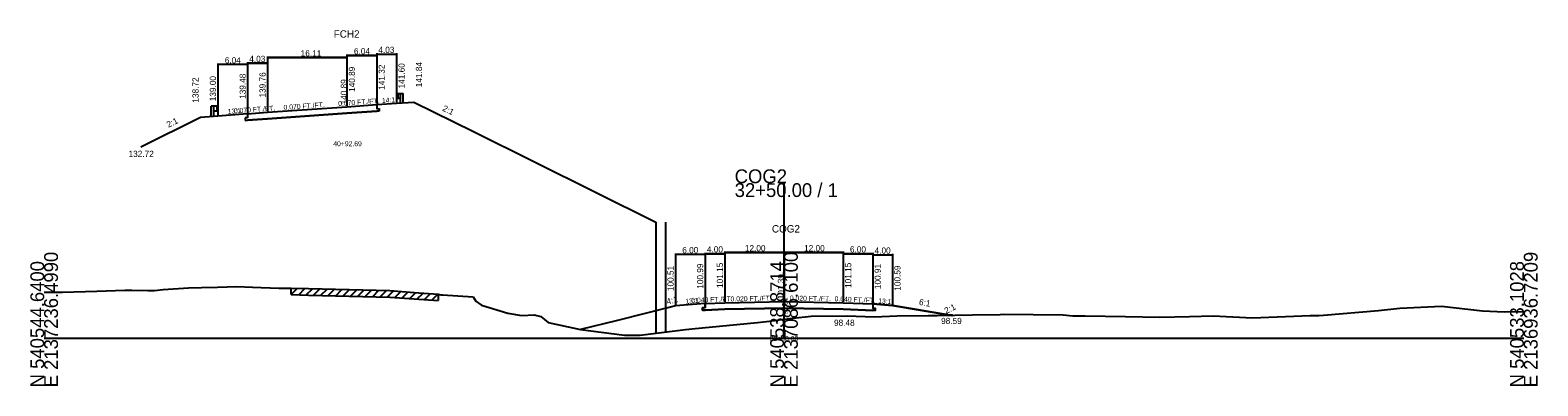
# Model space of a CAD drawing. Extents: x -13397 to 2303, y -10 to 39059.
# Drawn here: x 997.2 to 1302.8, y 4990.3 to 5062.4 of the extents above; entities that cross this region are included whole.
import ezdxf

# ---------------------------------------------------------------- set-up
doc = ezdxf.new("R2010")
doc.units = 0
for name, color, linetype in [('Level 20', 7, 'Continuous'), ('Level 5', 7, 'Continuous'), ('Level 53', 7, 'Continuous'), ('Level 54', 7, 'Continuous'), ('Level 55', 7, 'Continuous'), ('Level 7', 7, 'Continuous'), ('RD_GPK_XS_Cell', 7, 'Continuous'), ('RD_XS_EwShp', 7, 'Continuous'), ('RD_XS_ExGround', 7, 'Continuous'), ('RD_XS_ExPaveRet', 7, 'Continuous'), ('RD_XS_MedBWall', 7, 'Continuous'), ('RD_XS_Pave', 7, 'Continuous'), ('RD_XS_TX_Baseline', 7, 'Continuous'), ('RD_XS_TX_Elev_EX', 7, 'Continuous'), ('RD_XS_TX_Elev_PR', 7, 'Continuous'), ('RD_XS_TX_Station', 7, 'Continuous')]:
    doc.layers.add(name, color=color, linetype=linetype)

msp = doc.modelspace()

# ---------------------------------------------------------------- linework, layer by layer
at = {"layer": 'Level 20'}
for p, q in [((1045.28, 5057.04), (1045.28, 5045.96)), ((1045.28, 5057.04), (1045.28, 5045.96)), ((1045.28, 5057.04), (1045.28, 5045.96)), ((1045.28, 5057.04), (1045.28, 5045.96)), ((1045.28, 5056.84), (1061.39, 5056.84)), ((1045.28, 5056.84), (1061.39, 5056.84)), ((1061.39, 5056.84), (1045.28, 5056.84)), ((1061.39, 5056.84), (1045.28, 5056.84)), ((1061.39, 5057.47), (1061.39, 5047.09)), ((1061.39, 5057.47), (1061.39, 5047.09)), ((1061.39, 5057.47), (1061.39, 5047.09)), ((1061.39, 5057.27), (1067.42, 5057.27)), ((1067.42, 5057.27), (1061.39, 5057.27)), ((1067.42, 5057.27), (1061.39, 5057.27)), ((1061.39, 5057.04), (1061.39, 5047.09)), ((1061.39, 5057.04), (1061.39, 5047.09)), ((1061.39, 5057.04), (1061.39, 5047.09)), ((1061.39, 5057.04), (1061.39, 5047.09)), ((1067.42, 5057.75), (1067.42, 5047.52)), ((1067.42, 5057.55), (1071.45, 5057.55)), ((1067.42, 5057.47), (1067.42, 5047.52)), ((1067.42, 5057.47), (1067.42, 5047.52)), ((1067.42, 5057.47), (1067.42, 5047.52)), ((1071.45, 5057.75), (1071.45, 5047.8)), ((1035.21, 5055.63), (1035.21, 5045.2)), ((1041.25, 5055.43), (1035.21, 5055.43)), ((1041.25, 5055.91), (1041.25, 5045.68)), ((1041.25, 5055.91), (1041.25, 5045.68)), ((1041.25, 5055.91), (1041.25, 5045.68)), ((1041.25, 5055.71), (1045.28, 5055.71)), ((1041.25, 5055.71), (1045.28, 5055.71)), ((1045.28, 5055.71), (1041.25, 5055.71)), ((1041.25, 5055.63), (1041.25, 5045.68)), ((1045.28, 5055.91), (1045.28, 5045.96)), ((1045.28, 5055.91), (1045.28, 5045.96)), ((1045.28, 5055.91), (1045.28, 5045.96)), ((1033.87, 5045), (1033.87, 5046.99)), ((1034.43, 5046.99), (1033.87, 5046.99)), ((1034.43, 5045), (1034.43, 5046.99)), ((1034.98, 5046.99), (1034.43, 5046.99)), ((1034.98, 5046.99), (1034.98, 5046.01)), ((1035.06, 5046.91), (1034.98, 5046.92)), ((1035.19, 5046.81), (1035.07, 5046.91)), ((1045.28, 5045.76), (1061.39, 5046.89)), ((1061.39, 5046.89), (1067.42, 5047.32)), ((1067.42, 5047.32), (1071.45, 5047.6)), ((1067.42, 5047.32), (1067.42, 5046.48)), ((1071.45, 5047.6), (1074.97, 5047.84)), ((1071.48, 5049.41), (1071.59, 5049.5)), ((1071.48, 5049.31), (1071.59, 5049.22)), ((1071.48, 5048.88), (1071.59, 5048.97)), ((1071.48, 5048.78), (1071.59, 5048.69)), ((1071.6, 5049.51), (1071.68, 5049.52)), ((1071.6, 5048.68), (1071.68, 5048.67)), ((1071.61, 5049.17), (1071.61, 5049.02)), ((1071.68, 5049.58), (1071.68, 5048.61)), ((1071.68, 5049.58), (1072.23, 5049.58)), ((1071.68, 5048.61), (1072.23, 5048.61)), ((1072.23, 5047.6), (1072.23, 5049.58)), ((1072.23, 5049.58), (1072.79, 5049.58)), ((1072.79, 5047.6), (1072.79, 5049.58)), ((1074.97, 5047.84), (1087.05, 5041.84)), ((1031.69, 5044.72), (1019.6, 5038.72)), ((1035.21, 5045), (1031.69, 5044.72)), ((1034.98, 5046.01), (1034.43, 5046.01)), ((1035.06, 5046.09), (1034.98, 5046.07)), ((1035.05, 5046.58), (1035.05, 5046.42)), ((1035.19, 5046.71), (1035.07, 5046.62)), ((1035.19, 5046.28), (1035.07, 5046.38)), ((1035.19, 5046.18), (1035.07, 5046.09)), ((1041.25, 5045.48), (1035.21, 5045)), ((1041.25, 5044.64), (1040.75, 5044.61)), ((1040.75, 5044.61), (1040.75, 5044.11)), ((1040.75, 5044.11), (1041.25, 5044.14)), ((1041.25, 5045.48), (1045.28, 5045.76)), ((1041.25, 5045.48), (1041.25, 5044.64)), ((1045.28, 5044.43), (1041.25, 5044.14)), ((1045.28, 5044.43), (1041.25, 5044.14)), ((1041.25, 5044.14), (1045.28, 5044.43)), ((1061.39, 5045.56), (1045.28, 5044.43)), ((1061.39, 5045.56), (1045.28, 5044.43)), ((1045.28, 5044.43), (1061.39, 5045.56)), ((1045.28, 5044.43), (1061.39, 5045.56)), ((1067.42, 5045.98), (1061.39, 5045.56)), ((1061.39, 5045.56), (1067.42, 5045.98)), ((1061.39, 5045.56), (1067.42, 5045.98)), ((1067.42, 5046.48), (1067.93, 5046.52)), ((1067.93, 5046.02), (1067.42, 5045.98)), ((1067.93, 5046.52), (1067.93, 5046.02)), ((1087.05, 5041.84), (1124, 5023.49))]:
    msp.add_line(p, q, dxfattribs=at)
for centre, radius, start, end in [((1035.06, 5046.89), 0.026, 50.9495, 90), ((1035.14, 5046.76), 0.0651, 309.0337, 50.9664), ((1071.52, 5049.36), 0.0651, 129.0336, 230.9663), ((1071.52, 5048.83), 0.0651, 129.0336, 230.9663), ((1071.54, 5049.02), 0.0651, 302.9895, 0), ((1071.6, 5049.48), 0.026, 90, 129.0505), ((1071.54, 5049.17), 0.0651, 0, 45), ((1071.6, 5048.71), 0.026, 230.9496, 270), ((1035.12, 5046.58), 0.0651, 135, 180), ((1035.12, 5046.42), 0.0651, 180, 237.0105), ((1035.06, 5046.11), 0.026, 270, 309.0504), ((1035.14, 5046.23), 0.0651, 309.0337, 50.9664)]:
    msp.add_arc(centre, radius, start, end, dxfattribs=at)
at = {"layer": 'Level 5'}
for p, q in [((1134, 5006.16), (1133.5, 5006.14)), ((1133.5, 5006.14), (1133.5, 5005.64)), ((1133.5, 5005.64), (1134, 5005.66)), ((1134, 5006.99), (1134, 5006.16)), ((1138, 5005.82), (1134, 5005.66)), ((1138, 5005.82), (1134, 5005.66)), ((1138, 5005.82), (1134, 5005.66)), ((1134, 5005.66), (1138, 5005.82)), ((1150, 5006.06), (1138, 5005.82)), ((1150, 5006.06), (1138, 5005.82)), ((1150, 5006.06), (1138, 5005.82)), ((1138, 5005.82), (1150, 5006.06)), ((1138, 5005.82), (1150, 5006.06)), ((1162, 5005.82), (1150, 5006.06)), ((1162, 5005.82), (1150, 5006.06)), ((1150, 5006.06), (1162, 5005.82)), ((1150, 5006.06), (1162, 5005.82)), ((1150, 5006.06), (1162, 5005.82)), ((1168, 5005.58), (1162, 5005.82)), ((1162, 5005.82), (1168, 5005.58)), ((1162, 5005.82), (1168, 5005.58)), ((1162, 5005.82), (1168, 5005.58)), ((1168, 5006.91), (1168, 5006.08)), ((1168, 5006.08), (1168.5, 5006.06)), ((1168.5, 5005.56), (1168, 5005.58)), ((1168.5, 5006.06), (1168.5, 5005.56))]:
    msp.add_line(p, q, dxfattribs=at)
at = {"layer": 'Level 54'}
for p, q in [((1128, 5017.14), (1128, 5006.71)), ((1134, 5016.94), (1128, 5016.94)), ((1134, 5017.3), (1134, 5007.19)), ((1134, 5017.3), (1134, 5007.19)), ((1134, 5017.3), (1134, 5007.19)), ((1134, 5017.3), (1134, 5007.19)), ((1134, 5017.14), (1134, 5007.19)), ((1134, 5017.1), (1138, 5017.1)), ((1134, 5017.1), (1138, 5017.1)), ((1134, 5017.1), (1138, 5017.1)), ((1138, 5017.1), (1134, 5017.1)), ((1138, 5017.54), (1138, 5007.35)), ((1138, 5017.54), (1138, 5007.35)), ((1138, 5017.54), (1138, 5007.35)), ((1138, 5017.54), (1138, 5007.35)), ((1138, 5017.54), (1138, 5007.35)), ((1138, 5017.34), (1150, 5017.34)), ((1138, 5017.34), (1150, 5017.34)), ((1138, 5017.34), (1150, 5017.34)), ((1150, 5017.34), (1138, 5017.34)), ((1150, 5017.34), (1138, 5017.34)), ((1138, 5017.3), (1138, 5007.35)), ((1138, 5017.3), (1138, 5007.35)), ((1138, 5017.3), (1138, 5007.35)), ((1138, 5017.3), (1138, 5007.35)), ((1150, 5017.54), (1150, 5007.59)), ((1150, 5017.54), (1150, 5007.59)), ((1150, 5017.54), (1150, 5007.59)), ((1150, 5017.54), (1150, 5007.59)), ((1150, 5017.54), (1150, 5007.59)), ((1150, 5017.54), (1150, 5007.59)), ((1150, 5017.54), (1150, 5007.59)), ((1150, 5017.54), (1150, 5007.59)), ((1150, 5017.54), (1150, 5007.59)), ((1150, 5017.54), (1150, 5007.59)), ((1150, 5017.34), (1162, 5017.34)), ((1150, 5017.34), (1162, 5017.34)), ((1162, 5017.34), (1150, 5017.34)), ((1162, 5017.34), (1150, 5017.34)), ((1162, 5017.34), (1150, 5017.34)), ((1162, 5017.54), (1162, 5007.35)), ((1162, 5017.54), (1162, 5007.35)), ((1162, 5017.54), (1162, 5007.35)), ((1162, 5017.54), (1162, 5007.35)), ((1162, 5017.54), (1162, 5007.35)), ((1162, 5017.3), (1162, 5007.35)), ((1162, 5017.3), (1162, 5007.35)), ((1162, 5017.3), (1162, 5007.35)), ((1162, 5017.3), (1162, 5007.35)), ((1162, 5017.1), (1168, 5017.1)), ((1168, 5017.1), (1162, 5017.1)), ((1168, 5017.1), (1162, 5017.1)), ((1168, 5017.1), (1162, 5017.1)), ((1168, 5017.3), (1168, 5007.11)), ((1168, 5017.3), (1168, 5007.11)), ((1168, 5017.3), (1168, 5007.11)), ((1168, 5017.3), (1168, 5007.11)), ((1168, 5017.06), (1168, 5007.11)), ((1168, 5016.86), (1172, 5016.86)), ((1172, 5017.06), (1172, 5006.79))]:
    msp.add_line(p, q, dxfattribs=at)
at = {"layer": 'Level 7'}
for p, q in [((1128, 5006.51), (1126, 5006.01)), ((1126, 5006.01), (1126, 5001.24)), ((1134, 5006.99), (1128, 5006.51)), ((1168, 5006.91), (1172, 5006.59)), ((1172, 5006.59), (1184, 5004.59)), ((1184, 5004.59), (1184.13, 5004.65))]:
    msp.add_line(p, q, dxfattribs=at)
at = {"layer": 'RD_GPK_XS_Cell'}
for p, q in [((1150, 5000), (1150, 5031.39)), ((1000, 5000), (1150, 5000)), ((1150, 5000), (1300, 5000))]:
    msp.add_line(p, q, dxfattribs=at)
at = {"layer": 'RD_XS_EwShp'}
for points in [[(1117.63, 5000.6), (1119.5, 5000.57), (1120.82, 5000.6), (1130.02, 5001.73), (1130.76, 5001.83), (1131.32, 5001.88), (1144.64, 5003.16), (1147.04, 5003.42), (1150, 5003.81), (1151.78, 5004.05), (1155.48, 5004.43), (1162.82, 5004.48), (1168.26, 5004.33), (1172.92, 5004.51), (1179.27, 5004.6), (1181.05, 5004.6), (1183.67, 5004.65), (1172, 5006.59), (1168, 5006.91), (1168, 5006.08), (1168.5, 5006.06), (1168.5, 5005.56), (1168, 5005.58), (1162, 5005.82), (1150, 5006.06), (1138, 5005.82), (1134, 5005.66), (1133.5, 5005.64), (1133.5, 5006.14), (1134, 5006.16), (1134, 5006.99), (1128, 5006.51), (1116, 5003.51), (1108.76, 5001.7)], [(1183.67, 5004.65), (1184, 5004.59), (1184.13, 5004.65)]]:
    msp.add_lwpolyline(points, close=True, dxfattribs=at)
at = {"layer": 'RD_XS_ExGround'}
for p, q in [((1024.13, 5009.83), (1029.29, 5010.15)), ((1029.29, 5010.15), (1031.93, 5010.26)), ((1031.93, 5010.26), (1035.15, 5010.34)), ((1035.15, 5010.34), (1039.05, 5010.46)), ((1039.05, 5010.46), (1042.23, 5010.31)), ((1042.23, 5010.31), (1047.59, 5010.14)), ((1047.59, 5010.14), (1050.11, 5010.12)), ((1000, 5009.28), (1002.01, 5009.29)), ((1002.01, 5009.29), (1003.71, 5009.31)), ((1003.71, 5009.31), (1010.71, 5009.49)), ((1010.71, 5009.49), (1016.35, 5009.67)), ((1016.35, 5009.67), (1017.74, 5009.71)), ((1017.74, 5009.71), (1020.99, 5009.65)), ((1020.99, 5009.65), (1022.4, 5009.62)), ((1022.4, 5009.62), (1024.13, 5009.83)), ((1050.11, 5010.12), (1053.62, 5010.02)), ((1053.62, 5010.02), (1070.07, 5009.61)), ((1070.07, 5009.61), (1075.03, 5009.26)), ((1075.03, 5009.26), (1079.88, 5008.89)), ((1079.88, 5008.89), (1080.4, 5008.79)), ((1080.4, 5008.79), (1080.74, 5008.76)), ((1080.74, 5008.76), (1086.97, 5008.38)), ((1086.97, 5008.38), (1087.49, 5007.46)), ((1087.49, 5007.46), (1088.67, 5006.64)), ((1088.67, 5006.64), (1094.01, 5005.07)), ((1094.01, 5005.07), (1096.79, 5004.57)), ((1096.79, 5004.57), (1099.44, 5004.71)), ((1099.44, 5004.71), (1099.91, 5004.6)), ((1099.91, 5004.6), (1100.7, 5004.38)), ((1100.7, 5004.38), (1102.16, 5003.17)), ((1150, 5003.81), (1151.78, 5004.05)), ((1151.78, 5004.05), (1155.48, 5004.43)), ((1155.48, 5004.43), (1162.82, 5004.48)), ((1162.82, 5004.48), (1168.26, 5004.33)), ((1168.26, 5004.33), (1172.92, 5004.51)), ((1172.92, 5004.51), (1179.27, 5004.6)), ((1179.27, 5004.6), (1181.05, 5004.6)), ((1181.05, 5004.6), (1188.19, 5004.72)), ((1188.19, 5004.72), (1193.83, 5004.8)), ((1193.83, 5004.8), (1194.41, 5004.82)), ((1194.41, 5004.82), (1206.61, 5004.68)), ((1206.61, 5004.68), (1208.59, 5004.51)), ((1208.59, 5004.51), (1211.05, 5004.52)), ((1211.05, 5004.52), (1219.27, 5004.37)), ((1219.27, 5004.37), (1226.19, 5004.26)), ((1226.19, 5004.26), (1232.18, 5004.35)), ((1232.18, 5004.35), (1237.01, 5004.49)), ((1237.01, 5004.49), (1244.96, 5004.09)), ((1244.96, 5004.09), (1256.66, 5004.58)), ((1256.66, 5004.58), (1257.74, 5004.58)), ((1257.74, 5004.58), (1258.46, 5004.59)), ((1258.46, 5004.59), (1259.39, 5004.64)), ((1259.39, 5004.64), (1270.53, 5005.6)), ((1270.53, 5005.6), (1274.83, 5006.07)), ((1274.83, 5006.07), (1283.31, 5006.45)), ((1283.31, 5006.45), (1291.63, 5005.54)), ((1291.63, 5005.54), (1296.09, 5005.29)), ((1296.09, 5005.29), (1300, 5005.35)), ((1102.16, 5003.17), (1108.71, 5001.71)), ((1108.71, 5001.71), (1117.63, 5000.6)), ((1120.82, 5000.6), (1130.02, 5001.73)), ((1130.02, 5001.73), (1130.76, 5001.83)), ((1130.76, 5001.83), (1131.32, 5001.88)), ((1131.32, 5001.88), (1144.64, 5003.16)), ((1144.64, 5003.16), (1147.04, 5003.42)), ((1147.04, 5003.42), (1150, 5003.81)), ((1117.63, 5000.6), (1119.5, 5000.57)), ((1119.5, 5000.57), (1120.82, 5000.6))]:
    msp.add_line(p, q, dxfattribs=at)
at = {"layer": 'RD_XS_ExPaveRet'}
for p, q in [((1050.11, 5008.82), (1050.11, 5010.12)), ((1050.11, 5008.82), (1051.38, 5010.08)), ((1050.11, 5008.82), (1053.62, 5008.72)), ((1051.61, 5008.78), (1052.88, 5010.04)), ((1053.11, 5008.73), (1054.38, 5010)), ((1053.62, 5008.72), (1070.07, 5008.31)), ((1054.61, 5008.69), (1055.88, 5009.96)), ((1056.11, 5008.66), (1057.38, 5009.93)), ((1057.61, 5008.62), (1058.88, 5009.89)), ((1059.11, 5008.58), (1060.38, 5009.85)), ((1060.61, 5008.55), (1061.88, 5009.81)), ((1062.11, 5008.51), (1063.38, 5009.78)), ((1063.61, 5008.47), (1064.88, 5009.74)), ((1065.11, 5008.43), (1066.38, 5009.7)), ((1066.61, 5008.4), (1067.88, 5009.67)), ((1068.11, 5008.36), (1069.38, 5009.63)), ((1069.61, 5008.32), (1070.85, 5009.56)), ((1070.07, 5008.31), (1075.03, 5007.96)), ((1071.11, 5008.24), (1072.33, 5009.45)), ((1072.61, 5008.13), (1073.83, 5009.34)), ((1074.11, 5008.02), (1075.33, 5009.24)), ((1075.03, 5007.96), (1079.88, 5007.59)), ((1075.61, 5007.92), (1076.82, 5009.12)), ((1077.11, 5007.8), (1078.32, 5009.01)), ((1078.61, 5007.69), (1079.82, 5008.9)), ((1079.88, 5008.89), (1079.88, 5007.59))]:
    msp.add_line(p, q, dxfattribs=at)
at = {"layer": 'RD_XS_MedBWall'}
for p, q in [((1124, 5023.49), (1124, 5000.99)), ((1126, 5023.49), (1126, 5006.01))]:
    msp.add_line(p, q, dxfattribs=at)
at = {"layer": 'RD_XS_Pave'}
for p, q in [((1134, 5006.99), (1138, 5007.15)), ((1138, 5007.15), (1150, 5007.39)), ((1150, 5007.39), (1162, 5007.15)), ((1162, 5007.15), (1168, 5006.91))]:
    msp.add_line(p, q, dxfattribs=at)

# ---------------------------------------------------------------- texts
at = {"layer": 'Level 20'}
for s, height, p in [('FCH2', 1.5, (1058.7, 5060.89)), ('4.03', 1.25, (1067.76, 5057.8)), ('6.04', 1.25, (1036.62, 5055.68)), ('4.03', 1.25, (1041.59, 5055.96)), ('4.03', 1.25, (1041.59, 5055.96)), ('4.03', 1.25, (1041.59, 5055.96)), ('16.11', 1.25, (1052.01, 5057.09)), ('16.11', 1.25, (1052.01, 5057.09)), ('16.11', 1.25, (1052.01, 5057.09)), ('16.11', 1.25, (1052.01, 5057.09)), ('6.04', 1.25, (1062.8, 5057.52)), ('6.04', 1.25, (1062.8, 5057.52)), ('6.04', 1.25, (1062.8, 5057.52)), ('132.72', 1.25, (1017.11, 5036.72)), ('40+92.69', 1, (1058.61, 5038.89))]:
    msp.add_text(s, height=height, dxfattribs=at).set_placement(p)
for s, height, rotation, p in [('139.00', 1.25, 90, (1034.83, 5048)), ('139.48', 1.25, 90, (1040.87, 5048.48)), ('139.76', 1.25, 90, (1044.9, 5048.76)), ('139.76', 1.25, 90, (1044.9, 5048.76)), ('140.89', 1.25, 90, (1063.02, 5049.89)), ('140.89', 1.25, 90, (1063.02, 5049.89)), ('141.32', 1.25, 90, (1069.06, 5050.32)), ('141.60', 1.25, 90, (1073.08, 5050.6)), ('141.84', 1.25, 90, (1076.61, 5050.84)), ('138.72', 1.25, 90, (1031.3, 5047.72)), (' 140.89', 1.25, 90, (1061.39, 5046.89)), ('0.070 FT./FT.', 1, 4.0129, (1038.51, 5045.54)), ('0.070 FT./FT.', 1, 4.0129, (1038.51, 5045.54)), ('0.070 FT./FT.', 1, 4.0129, (1038.51, 5045.54)), ('0.070 FT./FT.', 1, 4.0147, (1048.57, 5046.24)), ('0.070 FT./FT.', 1, 4.0147, (1048.57, 5046.24)), ('0.070 FT./FT.', 1, 4.0147, (1048.57, 5046.24)), ('0.070 FT./FT.', 1, 4.0147, (1048.57, 5046.24)), ('0.070 FT./FT.', 1, 4.0167, (1059.65, 5047.02)), ('0.070 FT./FT.', 1, 4.0167, (1059.65, 5047.02)), ('0.070 FT./FT.', 1, 4.0167, (1059.65, 5047.02)), ('14:1', 1, 3.9907, (1068.52, 5047.64)), ('2:1', 1.25, 333.5843, (1080.62, 5046.16)), ('2:1', 1.25, 26.4087, (1025.2, 5042.61)), ('13:1', 1, 4.5429, (1037.26, 5045.41))]:
    msp.add_text(s, height=height, rotation=rotation, dxfattribs=at).set_placement(p)
at = {"layer": 'Level 53'}
for s, rotation, p in [('100.51', 90, (1127.62, 5009.51)), ('100.99', 90, (1133.62, 5009.99)), ('101.15', 90, (1137.63, 5010.15)), ('101.15', 90, (1137.63, 5010.15)), ('101.15', 90, (1137.63, 5010.15)), ('101.15', 90, (1163.62, 5010.15)), ('101.15', 90, (1163.62, 5010.15)), ('101.15', 90, (1163.62, 5010.15)), ('100.91', 90, (1169.62, 5009.91)), ('100.59', 90, (1173.62, 5009.59)), ('4:1', 14.0362, (1126.34, 5006.75)), ('6:1', 350.5377, (1177.3, 5006.72))]:
    msp.add_text(s, height=1.25, rotation=rotation, dxfattribs=at).set_placement(p)
for s, p in [('98.59', (1181.85, 5002.84)), ('98.48', (1160.14, 5002.48))]:
    msp.add_text(s, height=1.25, dxfattribs=at).set_placement(p)
at = {"layer": 'Level 54'}
for s, p in [('6.00', (1129.37, 5017.19)), ('4.00', (1134.37, 5017.35)), ('4.00', (1134.37, 5017.35)), ('4.00', (1134.37, 5017.35)), ('4.00', (1134.37, 5017.35)), ('12.00', (1142.07, 5017.59)), ('12.00', (1142.07, 5017.59)), ('12.00', (1142.07, 5017.59)), ('12.00', (1142.07, 5017.59)), ('12.00', (1142.07, 5017.59)), ('12.00', (1154.07, 5017.59)), ('12.00', (1154.07, 5017.59)), ('12.00', (1154.07, 5017.59)), ('12.00', (1154.07, 5017.59)), ('12.00', (1154.07, 5017.59)), ('6.00', (1163.37, 5017.35)), ('6.00', (1163.37, 5017.35)), ('6.00', (1163.37, 5017.35)), ('6.00', (1163.37, 5017.35)), ('4.00', (1168.37, 5017.11))]:
    msp.add_text(s, height=1.25, dxfattribs=at).set_placement(p)
at = {"layer": 'Level 55'}
for s, height, rotation, p in [('13:1', 1, 4.5739, (1130.03, 5006.92)), ('0.040 FT./FT.', 1, 2.2906, (1131.22, 5007.13)), ('0.040 FT./FT.', 1, 2.2906, (1131.22, 5007.13)), ('0.040 FT./FT.', 1, 2.2906, (1131.22, 5007.13)), ('0.040 FT./FT.', 1, 2.2906, (1131.22, 5007.13)), ('0.020 FT./FT.', 1, 1.1458, (1139.17, 5007.42)), ('0.020 FT./FT.', 1, 1.1458, (1139.17, 5007.42)), ('0.020 FT./FT.', 1, 1.1458, (1139.17, 5007.42)), ('0.020 FT./FT.', 1, 1.1458, (1139.17, 5007.42)), ('0.020 FT./FT.', 1, 1.1458, (1139.17, 5007.42)), ('0.020 FT./FT.', 1, 358.8542, (1151.18, 5007.62)), ('0.020 FT./FT.', 1, 358.8542, (1151.18, 5007.62)), ('0.020 FT./FT.', 1, 358.8542, (1151.18, 5007.62)), ('0.020 FT./FT.', 1, 358.8542, (1151.18, 5007.62)), ('0.020 FT./FT.', 1, 358.8542, (1151.18, 5007.62)), ('0.040 FT./FT.', 1, 357.7094, (1160.24, 5007.47)), ('0.040 FT./FT.', 1, 357.7094, (1160.24, 5007.47)), ('0.040 FT./FT.', 1, 357.7094, (1160.24, 5007.47)), ('0.040 FT./FT.', 1, 357.7094, (1160.24, 5007.47)), ('13:1', 1, 355.4261, (1169.07, 5007.08)), ('2:1', 1.25, 26.5651, (1182.89, 5004.87))]:
    msp.add_text(s, height=height, rotation=rotation, dxfattribs=at).set_placement(p)
at = {"layer": 'RD_GPK_XS_Cell'}
for s, p in [('32+50.00 / 1', (1140, 5028.59)), ('COG2', (1140, 5031.39))]:
    msp.add_text(s, height=2.8, dxfattribs=at).set_placement(p)
for s, p in [('E 2137236.4990', (1002.8, 4990)), ('E 2137086.6100', (1152.8, 4990)), ('E 2136936.7209', (1302.8, 4990)), ('N 540544.6400', (1000, 4990)), ('N 540538.8714', (1150, 4990)), ('N 540533.1028', (1300, 4990))]:
    msp.add_text(s, height=2.8, rotation=90, dxfattribs=at).set_placement(p)
at = {"layer": 'RD_XS_TX_Baseline'}
msp.add_text('COG2', height=1.5, dxfattribs=at).set_placement((1147.55, 5021.39))
at = {"layer": 'RD_XS_TX_Elev_EX'}
msp.add_text('97.81', height=1, rotation=90, dxfattribs=at).set_placement((1150.75, 5004.81))
at = {"layer": 'RD_XS_TX_Elev_PR'}
msp.add_text(' 101.39', height=1.25, rotation=90, dxfattribs=at).set_placement((1150, 5007.39))
at = {"layer": 'RD_XS_TX_Station'}
msp.add_text('32+50.00', height=1, dxfattribs=at).set_placement((1147.11, 4999.39))

doc.saveas('drawing.dxf')
